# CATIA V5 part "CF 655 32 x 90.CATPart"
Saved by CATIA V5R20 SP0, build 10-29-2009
Part number: CF 655 32 x 90
Definition: NONE
Nomenclature: CF 655 32 x 90
Source: Unknown
Description: CF 655 32 x 90
Bounding box of the stored display mesh (mm): x -64 to 26, y -26.5 to 26.5, z -26.5 to 26.5
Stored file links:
  C:\Users\Utente\Desktop\IO LAVORO\3D X SITO CF\X SITO\CF 655\CF 655 32 x 90.CATPart
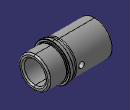
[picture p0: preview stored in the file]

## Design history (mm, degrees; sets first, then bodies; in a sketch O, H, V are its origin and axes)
Body1 "CF 655 32 x 90" (main body)
  Solid1: solid without history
